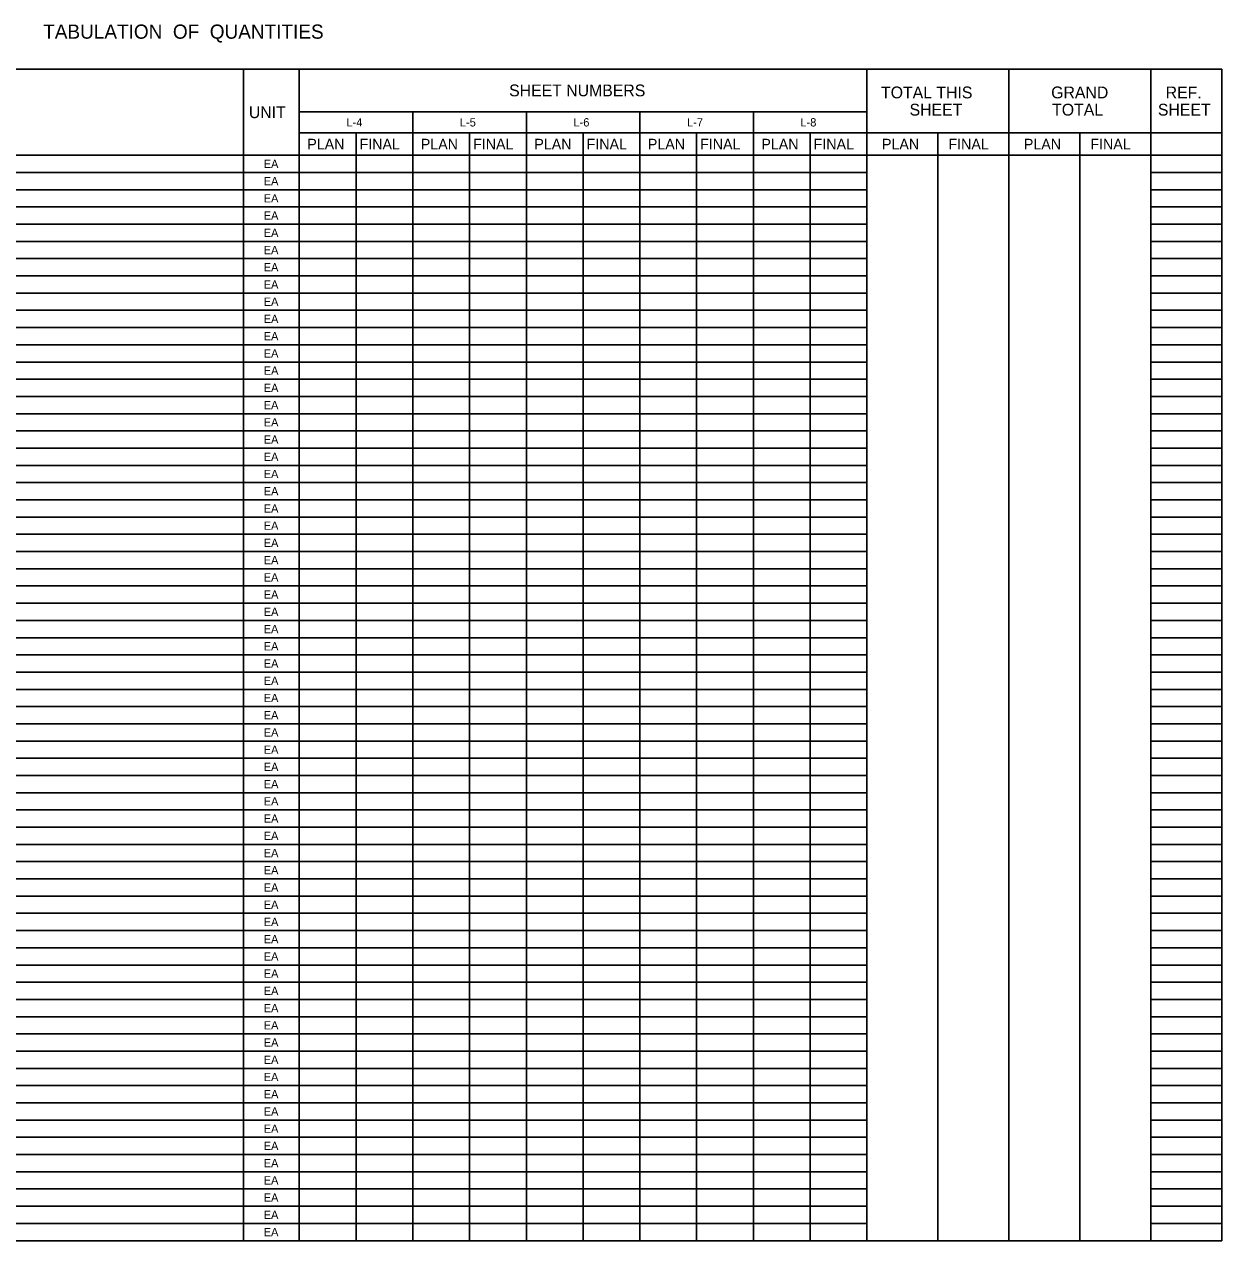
# Model space of a CAD drawing. Extents: x 56 to 1513, y -69 to 5602.
# Drawn here: x 598 to 1484, y 2393 to 3293 of the extents above; entities that cross this region are included whole.
import ezdxf

# ---------------------------------------------------------------- set-up
doc = ezdxf.new("R2010")
doc.units = 0
for name, color, linetype in [('SheetLines_dp', 7, 'Continuous'), ('TextCurveData', 7, 'Continuous'), ('TextMinor', 7, 'Continuous'), ('TextMisc', 7, 'Continuous')]:
    doc.layers.add(name, color=color, linetype=linetype)

msp = doc.modelspace()

# ---------------------------------------------------------------- linework, layer by layer
at = {"layer": 'SheetLines_dp'}
for p, q in [((760.09, 3260.27), (760.09, 2393.27)), ((760.09, 3260.27), (760.09, 2393.27)), ((801.34, 3260.27), (801.34, 3213.02)), ((801.34, 3260.27), (801.34, 2393.27)), ((1221.34, 3260.27), (1221.34, 2393.27)), ((1221.34, 3260.27), (1221.34, 2393.27)), ((1326.34, 3260.27), (1326.34, 2393.27)), ((1431.34, 3260.27), (1431.34, 2393.27)), ((1483.84, 3260.27), (1483.84, 2393.27)), ((801.34, 3228.77), (1221.34, 3228.77)), ((801.34, 3228.77), (1221.34, 3228.77)), ((885.34, 3228.77), (885.34, 2393.27)), ((885.34, 3228.77), (885.34, 2393.27)), ((969.34, 3228.77), (969.34, 2393.27)), ((969.34, 3228.77), (969.34, 3213.02)), ((1053.34, 3228.77), (1053.34, 2393.27)), ((1053.34, 3228.77), (1053.34, 3213.02)), ((1137.34, 3228.77), (1137.34, 2393.27)), ((1137.34, 3228.77), (1137.34, 2393.27)), ((801.34, 3213.02), (1483.84, 3213.02)), ((1221.34, 3213.02), (1483.84, 3213.02)), ((1326.34, 3213.02), (1326.34, 2393.27)), ((55.84, 3196.52), (1483.84, 3196.52)), ((801.34, 3196.52), (801.34, 2393.27)), ((969.34, 3196.52), (969.34, 2393.27)), ((1053.34, 3196.52), (1053.34, 2393.27)), ((1221.34, 3196.52), (1431.34, 3196.52)), ((1431.34, 3196.52), (1431.34, 2393.27)), ((55.84, 2393.27), (1483.84, 2393.27))]:
    msp.add_line(p, q, dxfattribs=at)
at = {"layer": 'TextMinor'}
for q in [(1431.34, 3260.27), (1483.84, 3260.27)]:
    msp.add_line((55.84, 3260.27), q, dxfattribs=at)
at = {"layer": 'TextMisc'}
for p, q in [((843.34, 3213.02), (843.34, 2393.27)), ((843.34, 3213.02), (843.34, 2393.27)), ((927.34, 3213.02), (927.34, 2393.27)), ((927.34, 3213.02), (927.34, 2393.27)), ((969.34, 3213.02), (969.34, 3196.52)), ((1011.34, 3213.02), (1011.34, 2393.27)), ((1011.34, 3213.02), (1011.34, 2393.27)), ((1053.34, 3213.02), (1053.34, 3196.52)), ((1095.34, 3213.02), (1095.34, 2393.27)), ((1095.34, 3213.02), (1095.34, 2393.27)), ((1179.34, 3213.02), (1179.34, 2393.27)), ((1179.34, 3213.02), (1179.34, 2393.27)), ((1273.84, 3213.02), (1273.84, 2393.27)), ((1273.84, 3213.02), (1273.84, 2393.27)), ((1378.84, 3213.02), (1378.84, 2393.27)), ((1378.84, 3213.02), (1378.84, 2393.27)), ((55.84, 3196.52), (1221.34, 3196.52)), ((1431.34, 3196.52), (1483.84, 3196.52)), ((55.84, 3183.77), (1221.34, 3183.77)), ((55.84, 3183.77), (1221.34, 3183.77)), ((1431.34, 3183.77), (1483.84, 3183.77)), ((1431.34, 3183.77), (1483.84, 3183.77)), ((55.84, 3171.02), (1221.34, 3171.02)), ((55.84, 3171.02), (1221.34, 3171.02)), ((1431.34, 3171.02), (1483.84, 3171.02)), ((1431.34, 3171.02), (1483.84, 3171.02)), ((55.84, 3158.27), (1221.34, 3158.27)), ((55.84, 3158.27), (1221.34, 3158.27)), ((1431.34, 3158.27), (1483.84, 3158.27)), ((1431.34, 3158.27), (1483.84, 3158.27)), ((55.84, 3145.52), (1221.34, 3145.52)), ((55.84, 3145.52), (1221.34, 3145.52)), ((1431.34, 3145.52), (1483.84, 3145.52)), ((1431.34, 3145.52), (1483.84, 3145.52)), ((55.84, 3132.77), (1221.34, 3132.77)), ((55.84, 3132.77), (1221.34, 3132.77)), ((1431.34, 3132.77), (1483.84, 3132.77)), ((1431.34, 3132.77), (1483.84, 3132.77)), ((55.84, 3120.02), (1221.34, 3120.02)), ((55.84, 3120.02), (1221.34, 3120.02)), ((1431.34, 3120.02), (1483.84, 3120.02)), ((1431.34, 3120.02), (1483.84, 3120.02)), ((55.84, 3107.27), (1221.34, 3107.27)), ((55.84, 3107.27), (1221.34, 3107.27)), ((1431.34, 3107.27), (1483.84, 3107.27)), ((1431.34, 3107.27), (1483.84, 3107.27)), ((55.84, 3094.52), (1221.34, 3094.52)), ((55.84, 3094.52), (1221.34, 3094.52)), ((1431.34, 3094.52), (1483.84, 3094.52)), ((1431.34, 3094.52), (1483.84, 3094.52)), ((55.84, 3081.77), (1221.34, 3081.77)), ((55.84, 3081.77), (1221.34, 3081.77)), ((1431.34, 3081.77), (1483.84, 3081.77)), ((1431.34, 3081.77), (1483.84, 3081.77)), ((55.84, 3069.02), (1221.34, 3069.02)), ((55.84, 3069.02), (1221.34, 3069.02)), ((1431.34, 3069.02), (1483.84, 3069.02)), ((1431.34, 3069.02), (1483.84, 3069.02)), ((55.84, 3056.27), (1221.34, 3056.27)), ((55.84, 3056.27), (1221.34, 3056.27)), ((1431.34, 3056.27), (1483.84, 3056.27)), ((1431.34, 3056.27), (1483.84, 3056.27)), ((55.84, 3043.52), (1221.34, 3043.52)), ((55.84, 3043.52), (1221.34, 3043.52)), ((1431.34, 3043.52), (1483.84, 3043.52)), ((1431.34, 3043.52), (1483.84, 3043.52)), ((55.84, 3030.77), (1221.34, 3030.77)), ((55.84, 3030.77), (1221.34, 3030.77)), ((1431.34, 3030.77), (1483.84, 3030.77)), ((1431.34, 3030.77), (1483.84, 3030.77)), ((55.84, 3018.02), (1221.34, 3018.02)), ((55.84, 3018.02), (1221.34, 3018.02)), ((1431.34, 3018.02), (1483.84, 3018.02)), ((1431.34, 3018.02), (1483.84, 3018.02)), ((55.84, 3005.27), (1221.34, 3005.27)), ((55.84, 3005.27), (1221.34, 3005.27)), ((1431.34, 3005.27), (1483.84, 3005.27)), ((1431.34, 3005.27), (1483.84, 3005.27)), ((55.84, 2992.52), (1221.34, 2992.52)), ((55.84, 2992.52), (1221.34, 2992.52)), ((1431.34, 2992.52), (1483.84, 2992.52)), ((1431.34, 2992.52), (1483.84, 2992.52)), ((55.84, 2979.77), (1221.34, 2979.77)), ((55.84, 2979.77), (1221.34, 2979.77)), ((1431.34, 2979.77), (1483.84, 2979.77)), ((1431.34, 2979.77), (1483.84, 2979.77)), ((55.84, 2967.02), (1221.34, 2967.02)), ((55.84, 2967.02), (1221.34, 2967.02)), ((1431.34, 2967.02), (1483.84, 2967.02)), ((1431.34, 2967.02), (1483.84, 2967.02)), ((55.84, 2954.27), (1221.34, 2954.27)), ((55.84, 2954.27), (1221.34, 2954.27)), ((1431.34, 2954.27), (1483.84, 2954.27)), ((1431.34, 2954.27), (1483.84, 2954.27)), ((55.84, 2941.52), (1221.34, 2941.52)), ((55.84, 2941.52), (1221.34, 2941.52)), ((1431.34, 2941.52), (1483.84, 2941.52)), ((1431.34, 2941.52), (1483.84, 2941.52)), ((55.84, 2928.77), (1221.34, 2928.77)), ((55.84, 2928.77), (1221.34, 2928.77)), ((1431.34, 2928.77), (1483.84, 2928.77)), ((1431.34, 2928.77), (1483.84, 2928.77)), ((55.84, 2916.02), (1221.34, 2916.02)), ((55.84, 2916.02), (1221.34, 2916.02)), ((1431.34, 2916.02), (1483.84, 2916.02)), ((1431.34, 2916.02), (1483.84, 2916.02)), ((55.84, 2903.27), (1221.34, 2903.27)), ((55.84, 2903.27), (1221.34, 2903.27)), ((1431.34, 2903.27), (1483.84, 2903.27)), ((1431.34, 2903.27), (1483.84, 2903.27)), ((55.84, 2890.52), (1221.34, 2890.52)), ((55.84, 2890.52), (1221.34, 2890.52)), ((1431.34, 2890.52), (1483.84, 2890.52)), ((1431.34, 2890.52), (1483.84, 2890.52)), ((55.84, 2877.77), (1221.34, 2877.77)), ((55.84, 2877.77), (1221.34, 2877.77)), ((1431.34, 2877.77), (1483.84, 2877.77)), ((1431.34, 2877.77), (1483.84, 2877.77)), ((55.84, 2865.02), (1221.34, 2865.02)), ((55.84, 2865.02), (1221.34, 2865.02)), ((1431.34, 2865.02), (1483.84, 2865.02)), ((1431.34, 2865.02), (1483.84, 2865.02)), ((55.84, 2852.27), (1221.34, 2852.27)), ((55.84, 2852.27), (1221.34, 2852.27)), ((1431.34, 2852.27), (1483.84, 2852.27)), ((1431.34, 2852.27), (1483.84, 2852.27)), ((55.84, 2839.52), (1221.34, 2839.52)), ((55.84, 2839.52), (1221.34, 2839.52)), ((1431.34, 2839.52), (1483.84, 2839.52)), ((1431.34, 2839.52), (1483.84, 2839.52)), ((55.84, 2826.77), (1221.34, 2826.77)), ((55.84, 2826.77), (1221.34, 2826.77)), ((1431.34, 2826.77), (1483.84, 2826.77)), ((1431.34, 2826.77), (1483.84, 2826.77)), ((55.84, 2814.02), (1221.34, 2814.02)), ((55.84, 2814.02), (1221.34, 2814.02)), ((1431.34, 2814.02), (1483.84, 2814.02)), ((1431.34, 2814.02), (1483.84, 2814.02)), ((55.84, 2801.27), (1221.34, 2801.27)), ((55.84, 2801.27), (1221.34, 2801.27)), ((1431.34, 2801.27), (1483.84, 2801.27)), ((1431.34, 2801.27), (1483.84, 2801.27)), ((55.84, 2788.52), (1221.34, 2788.52)), ((55.84, 2788.52), (1221.34, 2788.52)), ((1431.34, 2788.52), (1483.84, 2788.52)), ((1431.34, 2788.52), (1483.84, 2788.52)), ((55.84, 2775.77), (1221.34, 2775.77)), ((55.84, 2775.77), (1221.34, 2775.77)), ((1431.34, 2775.77), (1483.84, 2775.77)), ((1431.34, 2775.77), (1483.84, 2775.77)), ((55.84, 2763.02), (1221.34, 2763.02)), ((55.84, 2763.02), (1221.34, 2763.02)), ((1431.34, 2763.02), (1483.84, 2763.02)), ((1431.34, 2763.02), (1483.84, 2763.02)), ((55.84, 2750.27), (1221.34, 2750.27)), ((55.84, 2750.27), (1221.34, 2750.27)), ((1431.34, 2750.27), (1483.84, 2750.27)), ((1431.34, 2750.27), (1483.84, 2750.27)), ((55.84, 2737.52), (1221.34, 2737.52)), ((55.84, 2737.52), (1221.34, 2737.52)), ((1431.34, 2737.52), (1483.84, 2737.52)), ((1431.34, 2737.52), (1483.84, 2737.52)), ((55.84, 2724.77), (1221.34, 2724.77)), ((55.84, 2724.77), (1221.34, 2724.77)), ((1431.34, 2724.77), (1483.84, 2724.77)), ((1431.34, 2724.77), (1483.84, 2724.77)), ((55.84, 2712.02), (1221.34, 2712.02)), ((55.84, 2712.02), (1221.34, 2712.02)), ((1431.34, 2712.02), (1483.84, 2712.02)), ((1431.34, 2712.02), (1483.84, 2712.02)), ((55.84, 2699.27), (1221.34, 2699.27)), ((55.84, 2699.27), (1221.34, 2699.27)), ((1431.34, 2699.27), (1483.84, 2699.27)), ((1431.34, 2699.27), (1483.84, 2699.27)), ((55.84, 2686.52), (1221.34, 2686.52)), ((55.84, 2686.52), (1221.34, 2686.52)), ((1431.34, 2686.52), (1483.84, 2686.52)), ((1431.34, 2686.52), (1483.84, 2686.52)), ((55.84, 2673.77), (1221.34, 2673.77)), ((55.84, 2673.77), (1221.34, 2673.77)), ((1431.34, 2673.77), (1483.84, 2673.77)), ((1431.34, 2673.77), (1483.84, 2673.77)), ((55.84, 2661.02), (1221.34, 2661.02)), ((55.84, 2661.02), (1221.34, 2661.02)), ((1431.34, 2661.02), (1483.84, 2661.02)), ((1431.34, 2661.02), (1483.84, 2661.02)), ((55.84, 2648.27), (1221.34, 2648.27)), ((55.84, 2648.27), (1221.34, 2648.27)), ((1431.34, 2648.27), (1483.84, 2648.27)), ((1431.34, 2648.27), (1483.84, 2648.27)), ((55.84, 2635.52), (1221.34, 2635.52)), ((55.84, 2635.52), (1221.34, 2635.52)), ((1431.34, 2635.52), (1483.84, 2635.52)), ((1431.34, 2635.52), (1483.84, 2635.52)), ((55.84, 2622.77), (1221.34, 2622.77)), ((55.84, 2622.77), (1221.34, 2622.77)), ((1431.34, 2622.77), (1483.84, 2622.77)), ((1431.34, 2622.77), (1483.84, 2622.77)), ((55.84, 2610.02), (1221.34, 2610.02)), ((55.84, 2610.02), (1221.34, 2610.02)), ((1431.34, 2610.02), (1483.84, 2610.02)), ((1431.34, 2610.02), (1483.84, 2610.02)), ((55.84, 2597.27), (1221.34, 2597.27)), ((55.84, 2597.27), (1221.34, 2597.27)), ((1431.34, 2597.27), (1483.84, 2597.27)), ((1431.34, 2597.27), (1483.84, 2597.27)), ((55.84, 2584.52), (1221.34, 2584.52)), ((55.84, 2584.52), (1221.34, 2584.52)), ((1431.34, 2584.52), (1483.84, 2584.52)), ((1431.34, 2584.52), (1483.84, 2584.52)), ((55.84, 2571.77), (1221.34, 2571.77)), ((55.84, 2571.77), (1221.34, 2571.77)), ((1431.34, 2571.77), (1483.84, 2571.77)), ((1431.34, 2571.77), (1483.84, 2571.77)), ((55.84, 2559.02), (1221.34, 2559.02)), ((55.84, 2559.02), (1221.34, 2559.02)), ((1431.34, 2559.02), (1483.84, 2559.02)), ((1431.34, 2559.02), (1483.84, 2559.02)), ((55.84, 2546.27), (1221.34, 2546.27)), ((55.84, 2546.27), (1221.34, 2546.27)), ((1431.34, 2546.27), (1483.84, 2546.27)), ((1431.34, 2546.27), (1483.84, 2546.27)), ((55.84, 2533.52), (1221.34, 2533.52)), ((55.84, 2533.52), (1221.34, 2533.52)), ((1431.34, 2533.52), (1483.84, 2533.52)), ((1431.34, 2533.52), (1483.84, 2533.52)), ((55.84, 2520.77), (1221.34, 2520.77)), ((55.84, 2520.77), (1221.34, 2520.77)), ((1431.34, 2520.77), (1483.84, 2520.77)), ((1431.34, 2520.77), (1483.84, 2520.77)), ((55.84, 2508.02), (1221.34, 2508.02)), ((55.84, 2508.02), (1221.34, 2508.02)), ((1431.34, 2508.02), (1483.84, 2508.02)), ((1431.34, 2508.02), (1483.84, 2508.02)), ((55.84, 2495.27), (1221.34, 2495.27)), ((55.84, 2495.27), (1221.34, 2495.27)), ((1431.34, 2495.27), (1483.84, 2495.27)), ((1431.34, 2495.27), (1483.84, 2495.27)), ((55.84, 2482.52), (1221.34, 2482.52)), ((55.84, 2482.52), (1221.34, 2482.52)), ((1431.34, 2482.52), (1483.84, 2482.52)), ((1431.34, 2482.52), (1483.84, 2482.52)), ((55.84, 2469.77), (1221.34, 2469.77)), ((55.84, 2469.77), (1221.34, 2469.77)), ((1431.34, 2469.77), (1483.84, 2469.77)), ((1431.34, 2469.77), (1483.84, 2469.77)), ((55.84, 2457.02), (1221.34, 2457.02)), ((55.84, 2457.02), (1221.34, 2457.02)), ((1431.34, 2457.02), (1483.84, 2457.02)), ((1431.34, 2457.02), (1483.84, 2457.02)), ((55.84, 2444.27), (1221.34, 2444.27)), ((55.84, 2444.27), (1221.34, 2444.27)), ((1431.34, 2444.27), (1483.84, 2444.27)), ((1431.34, 2444.27), (1483.84, 2444.27)), ((55.84, 2431.52), (1221.34, 2431.52)), ((55.84, 2431.52), (1221.34, 2431.52)), ((1431.34, 2431.52), (1483.84, 2431.52)), ((1431.34, 2431.52), (1483.84, 2431.52)), ((55.84, 2418.77), (1221.34, 2418.77)), ((55.84, 2418.77), (1221.34, 2418.77)), ((1431.34, 2418.77), (1483.84, 2418.77)), ((1431.34, 2418.77), (1483.84, 2418.77)), ((55.84, 2406.02), (1221.34, 2406.02)), ((55.84, 2406.02), (1221.34, 2406.02)), ((1431.34, 2406.02), (1483.84, 2406.02)), ((1431.34, 2406.02), (1483.84, 2406.02))]:
    msp.add_line(p, q, dxfattribs=at)

# ---------------------------------------------------------------- texts
at = {"layer": 'TextCurveData'}
for s, height, p in [('TABULATION  OF  QUANTITIES', 10.5, (611.83, 3282.77)), ('SHEET NUMBERS', 8.75, (956.59, 3240.14)), ('TOTAL THIS', 8.75, (1231.79, 3238.64)), ('GRAND', 8.75, (1357.7, 3238.64)), ('REF.', 8.75, (1442.4, 3238.64)), ('UNIT', 8.75, (764, 3224.02)), ('SHEET', 8.75, (1252.89, 3225.89)), ('TOTAL', 8.75, (1358.38, 3225.89)), ('SHEET', 8.75, (1436.64, 3225.89)), ('L-4', 6.125, (836.2, 3217.83)), ('L-5', 6.125, (920.11, 3217.83)), ('L-6', 6.125, (1004.15, 3217.83)), ('L-7', 6.125, (1088.22, 3217.83)), ('L-8', 6.125, (1172.1, 3217.83)), ('PLAN', 7.875, (807.24, 3200.83)), ('FINAL', 7.875, (845.93, 3200.83)), ('PLAN', 7.875, (891.24, 3200.83)), ('FINAL', 7.875, (929.93, 3200.83)), ('PLAN', 7.875, (975.24, 3200.83)), ('FINAL', 7.875, (1013.93, 3200.83)), ('PLAN', 7.875, (1059.24, 3200.83)), ('FINAL', 7.875, (1097.93, 3200.83)), ('PLAN', 7.875, (1143.24, 3200.83)), ('FINAL', 7.875, (1181.93, 3200.83)), ('PLAN', 7.875, (1232.49, 3200.83)), ('FINAL', 7.875, (1281.68, 3200.83)), ('PLAN', 7.875, (1337.49, 3200.83)), ('FINAL', 7.875, (1386.68, 3200.83)), ('EA', 6.125, (774.96, 3187.08)), ('EA', 6.125, (774.96, 3174.33)), ('EA', 6.125, (774.96, 3161.58)), ('EA', 6.125, (774.96, 3148.83)), ('EA', 6.125, (774.96, 3136.08)), ('EA', 6.125, (774.96, 3123.33)), ('EA', 6.125, (774.96, 3110.58)), ('EA', 6.125, (774.96, 3097.83)), ('EA', 6.125, (774.96, 3085.08)), ('EA', 6.125, (774.96, 3072.33)), ('EA', 6.125, (774.96, 3059.58)), ('EA', 6.125, (774.96, 3046.83)), ('EA', 6.125, (774.96, 3034.08)), ('EA', 6.125, (774.96, 3021.33)), ('EA', 6.125, (774.96, 3008.58)), ('EA', 6.125, (774.96, 2995.83)), ('EA', 6.125, (774.96, 2983.08)), ('EA', 6.125, (774.96, 2970.33)), ('EA', 6.125, (774.96, 2957.58)), ('EA', 6.125, (774.96, 2944.83)), ('EA', 6.125, (774.96, 2932.08)), ('EA', 6.125, (774.96, 2919.33)), ('EA', 6.125, (774.96, 2906.58)), ('EA', 6.125, (774.96, 2893.83)), ('EA', 6.125, (774.96, 2881.08)), ('EA', 6.125, (774.96, 2868.33)), ('EA', 6.125, (774.96, 2855.58)), ('EA', 6.125, (774.96, 2842.83)), ('EA', 6.125, (774.96, 2830.08)), ('EA', 6.125, (774.96, 2817.33)), ('EA', 6.125, (774.96, 2804.58)), ('EA', 6.125, (774.96, 2791.83)), ('EA', 6.125, (774.96, 2779.08)), ('EA', 6.125, (774.96, 2766.33)), ('EA', 6.125, (774.96, 2753.58)), ('EA', 6.125, (774.96, 2740.83)), ('EA', 6.125, (774.96, 2728.08)), ('EA', 6.125, (774.96, 2715.33)), ('EA', 6.125, (774.96, 2702.58)), ('EA', 6.125, (774.96, 2689.83)), ('EA', 6.125, (774.96, 2677.08)), ('EA', 6.125, (774.96, 2664.33)), ('EA', 6.125, (774.96, 2651.58)), ('EA', 6.125, (774.96, 2638.83)), ('EA', 6.125, (774.96, 2626.08)), ('EA', 6.125, (774.96, 2613.33)), ('EA', 6.125, (774.96, 2600.58)), ('EA', 6.125, (774.96, 2587.83)), ('EA', 6.125, (774.96, 2575.08)), ('EA', 6.125, (774.96, 2562.33)), ('EA', 6.125, (774.96, 2549.58)), ('EA', 6.125, (774.96, 2536.83)), ('EA', 6.125, (774.96, 2524.08)), ('EA', 6.125, (774.96, 2511.33)), ('EA', 6.125, (774.96, 2498.58)), ('EA', 6.125, (774.96, 2485.83)), ('EA', 6.125, (774.96, 2473.08)), ('EA', 6.125, (774.96, 2460.33)), ('EA', 6.125, (774.96, 2447.58)), ('EA', 6.125, (774.96, 2434.83)), ('EA', 6.125, (774.96, 2422.08)), ('EA', 6.125, (774.96, 2409.33)), ('EA', 6.125, (774.96, 2396.58))]:
    msp.add_text(s, height=height, dxfattribs=at).set_placement(p)

doc.saveas('drawing.dxf')
